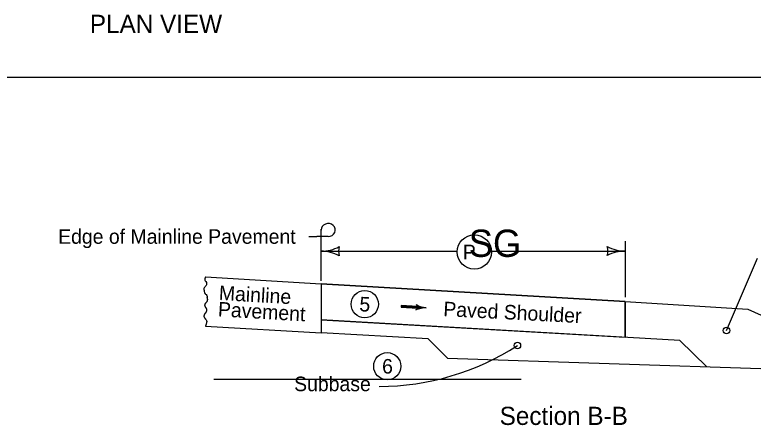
# Model space of a CAD drawing. Extents: x 9538 to 81668, y 7600 to 11751.
# Drawn here: x 14667 to 15480, y 8978 to 9430 of the extents above; entities that cross this region are included whole.
import ezdxf

# ---------------------------------------------------------------- set-up
doc = ezdxf.new("R2010")
doc.units = 0
for name, color, linetype in [('DsnShtMinorGrid13', 7, 'Continuous'), ('DsnShtMinorGrid14', 7, 'Continuous'), ('dsnStdDimension', 7, 'Continuous'), ('dsnStdNameDate', 7, 'Continuous'), ('dsnStdNote', 7, 'Continuous'), ('dsnStdTable', 7, 'Continuous')]:
    doc.layers.add(name, color=color, linetype=linetype)

msp = doc.modelspace()

# ---------------------------------------------------------------- linework, layer by layer
at = {"layer": 'DsnShtMinorGrid13'}
for centre in [(15052.15, 9111.48), (15077, 9043.19)]:
    msp.add_circle(centre, 15, dxfattribs=at)
at = {"layer": 'DsnShtMinorGrid14'}
for centre in [(15450.71, 9082.58), (15220.39, 9066.08)]:
    msp.add_circle(centre, 3.54, dxfattribs=at)
at = {"layer": 'dsnStdDimension'}
for p, q in [((15339.25, 9119.12), (15339.25, 9180.8)), ((15004.03, 9169.81), (15154.03, 9169.81)), ((15191.85, 9169.96), (15339.25, 9169.96))]:
    msp.add_line(p, q, dxfattribs=at)
msp.add_circle((15172.95, 9168.99), 18.93, dxfattribs=at)
for centre, radius, start, end in [((15004.03, 9212.31), 42.5, 270, 298.07249), ((15004.03, 9127.31), 42.5, 61.92751, 90), ((15039.67, 9169.81), 16.42, 162.26665, 197.73335), ((15303.62, 9169.96), 16.42, 342.26665, 17.73335), ((15339.25, 9212.46), 42.5, 241.92751, 270), ((15339.25, 9127.46), 42.5, 90, 118.07249), ((15067.44, 9303.03), 282.03, 270.13198, 302.84273)]:
    msp.add_arc(centre, radius, start, end, dxfattribs=at)
at = {"layer": 'dsnStdNameDate'}
msp.add_line((15903.11, 9361.02), (13747.53, 9361.02), dxfattribs=at)
at = {"layer": 'dsnStdNote'}
for p, q in [((15004.03, 9173.13), (15004.03, 9193.99)), ((14990.66, 9185.97), (14999.35, 9185.97)), ((15011.84, 9185.97), (14999.35, 9185.97)), ((15004.03, 9137.19), (15004.03, 9173.13)), ((15450.71, 9082.58), (15484.98, 9162)), ((15110.42, 9108.09), (15092.21, 9109.14)), ((15110.31, 9107.15), (15110.31, 9107.15)), ((15110.43, 9109.09), (15110.43, 9109.09))]:
    msp.add_line(p, q, dxfattribs=at)
for points in [[(15110.44, 9109.03), (15092.28, 9110.08), (15092.15, 9108.2), (15110.31, 9107.15), (15110.37, 9108.76), (15092.5, 9109.86), (15092.44, 9108.36), (15109.93, 9107.41), (15110.05, 9108.53), (15092.73, 9109.59), (15092.71, 9108.59), (15109.72, 9107.61), (15109.81, 9108.32), (15092.92, 9109.37), (15092.9, 9108.81), (15109.51, 9107.87)], [(15110.04, 9110.28), (15110.73, 9109.12), (15110.71, 9107.47), (15109.95, 9106.07), (15112.71, 9106.94), (15115.9, 9107.59), (15116.8, 9107.72), (15114.56, 9108.27), (15111.33, 9109.5), (15110.39, 9110.03), (15110.51, 9106.52), (15115.46, 9107.74), (15110.82, 9109.32), (15110.83, 9106.9), (15114.23, 9107.83), (15111.23, 9108.69), (15111, 9107.31), (15113.16, 9107.81), (15111.57, 9108.32), (15111.43, 9107.66), (15112.22, 9107.82)]]:
    msp.add_lwpolyline(points, dxfattribs=at)
for centre, major_axis, start_param, end_param in [((15011.84, 9193.11), (-7.81, 0), 1.570796, 6.283185), ((15106.65, 9108.3), (3.88, 0), 5.202895, 7.237436), ((15121.71, 9127.73), (-22.17, 0), 0.954258, 1.478381), ((15118.92, 9087.31), (22.17, 0), 1.537172, 2.061295)]:
    msp.add_ellipse(centre, major_axis=major_axis, ratio=0.913811, start_param=start_param, end_param=end_param, dxfattribs=at)
at = {"layer": 'dsnStdTable'}
for p, q in [((14876.57, 9141.46), (15004.03, 9134.05)), ((15004.03, 9134.05), (15004.03, 9080.04)), ((15004.03, 9134.05), (15339.17, 9114.56)), ((15339.17, 9114.56), (15004.03, 9134.05)), ((15004.03, 9134.05), (15004.03, 9094.45)), ((15339.17, 9114.56), (15474.01, 9106.17)), ((15339.17, 9075.13), (15339.17, 9114.56)), ((15339.17, 9114.56), (15339.17, 9075.13)), ((15474.01, 9106.17), (15626.55, 9036.24)), ((14876.6, 9087.45), (15004.03, 9080.04)), ((15399.17, 9071.67), (15004.03, 9094.45)), ((15004.03, 9094.45), (15339.17, 9075.13)), ((15121.87, 9073.24), (15004.03, 9080.04)), ((15121.87, 9073.24), (15143.21, 9052.03)), ((15399.17, 9071.67), (15429.03, 9042.69)), ((15143.21, 9052.03), (15626.55, 9036.24)), ((14885.98, 9029.13), (15224.48, 9029.13))]:
    msp.add_line(p, q, dxfattribs=at)
msp.add_circle((15052.15, 9111.48), 15, dxfattribs=at)
for points in [[(14876.57, 9141.46), (14876.06, 9137.86), (14877.11, 9136.35), (14877.97, 9134.06), (14877.37, 9132), (14875.46, 9129.62), (14874.94, 9127.72), (14875.46, 9125.43), (14876.33, 9123.05), (14877.37, 9122.34), (14878.75, 9119.8), (14878.74, 9118.96)], [(14876.78, 9101.85), (14876.99, 9102.1), (14877.19, 9102.36), (14877.54, 9102.92), (14877.82, 9103.51), (14877.94, 9103.82), (14878.04, 9104.13), (14878.17, 9104.75), (14878.22, 9105.37), (14878.17, 9105.96), (14878.11, 9106.24), (14878.07, 9106.37), (14878.03, 9106.5), (14877.82, 9106.88), (14877.54, 9107.24), (14877.24, 9107.61), (14876.99, 9108.01), (14876.85, 9108.29), (14876.71, 9108.57), (14876.45, 9109.15), (14876.25, 9109.71), (14876.18, 9110.01), (14876.12, 9110.3), (14876.11, 9110.43), (14876.11, 9110.56), (14876.26, 9111.33), (14876.47, 9111.85), (14876.73, 9112.36), (14877.17, 9113), (14877.69, 9113.54), (14878.21, 9114.09), (14878.44, 9114.4), (14878.64, 9114.74), (14878.84, 9115.21), (14879, 9115.68), (14879.1, 9116.16), (14879.13, 9116.4), (14879.15, 9116.52), (14879.16, 9116.64), (14879.11, 9117.15), (14878.96, 9117.66), (14878.91, 9117.79), (14878.85, 9117.91), (14878.8, 9118.04), (14878.78, 9118.17), (14878.74, 9118.96)], [(14876.78, 9101.85), (14876.56, 9101.62), (14876.32, 9101.38), (14876.08, 9101.14), (14875.9, 9100.87), (14875.76, 9100.59), (14875.62, 9100.3), (14875.36, 9099.73), (14875.25, 9099.45), (14875.15, 9099.16), (14875.08, 9098.87), (14875.05, 9098.72), (14875.03, 9098.57), (14875.04, 9098.06), (14875.17, 9097.54), (14875.38, 9097.02), (14875.64, 9096.51), (14876.08, 9095.88), (14876.6, 9095.33), (14877.12, 9094.78), (14877.35, 9094.48), (14877.55, 9094.14), (14877.95, 9093.19), (14878.06, 9092.72), (14878.07, 9092.24), (14878.03, 9091.95), (14877.98, 9091.66), (14877.93, 9091.37), (14877.86, 9091.09), (14877.55, 9089.94), (14877.37, 9089.33), (14877.17, 9088.73), (14876.95, 9088.14), (14876.82, 9087.85), (14876.68, 9087.57), (14876.6, 9087.45)]]:
    msp.add_spline(points, degree=3, dxfattribs=at)

# ---------------------------------------------------------------- texts
at = {"layer": 'DsnShtMinorGrid13'}
msp.add_text('5', height=16, rotation=356.69973, dxfattribs=at).set_placement((15045.93, 9103.82))
msp.add_text('6', height=16, dxfattribs=at).set_placement((15071.29, 9035.19))
at = {"layer": 'dsnStdDimension'}
for s, height, p in [('SG', 30, (15166.66, 9163.55)), ('P', 16, (15160.23, 9160.99))]:
    msp.add_text(s, height=height, dxfattribs=at).set_placement(p)
at = {"layer": 'dsnStdNote'}
for s, height, p in [('PLAN VIEW', 20, (14749.39, 9409.91)), ('Edge of Mainline Pavement', 16, (14714.42, 9177.97)), ('Subbase', 16, (14974.38, 9015.81)), ('Section B-B', 20, (15200.77, 8978.66))]:
    msp.add_text(s, height=height, dxfattribs=at).set_placement(p)
for s, rotation, p in [('Mainline', 356.73462, (14891.16, 9116.12)), ('Pavement', 356.73462, (14890.14, 9098.15)), ('Paved Shoulder ', 357.0678, (15138.43, 9098.45))]:
    msp.add_text(s, height=16, rotation=rotation, dxfattribs=at).set_placement(p)

doc.saveas('drawing.dxf')
